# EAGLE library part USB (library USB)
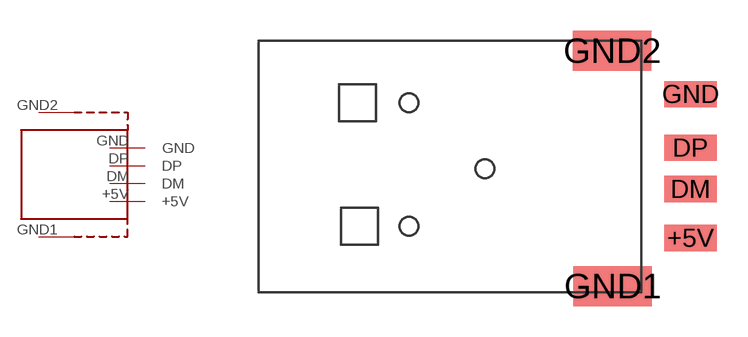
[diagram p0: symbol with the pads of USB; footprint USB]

Designator prefix -

## USB  [USB]
+5V  +5V  pwr
DM  DM
DP  DP
GND  GND  pwr
GND1  GND1  pwr
GND2  GND2

## Footprint USB (pad centres in mm)
smd 2.54 x 1.27: +5V 6.78,-3.27; DM 6.78,-0.895; DP 6.78,1.11; GND 6.78,3.715
smd 3.81 x 1.93: GND1 3.005,-5.61; GND2 2.97,5.82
